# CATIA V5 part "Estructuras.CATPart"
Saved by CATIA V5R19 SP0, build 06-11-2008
Part number: Estructuras
Bounding box of the stored display mesh (mm): x -165.206 to 53.773, y -15.481 to 36, z -5 to 20
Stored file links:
  G:\Prácticas\0068\68_v5r19\Estructuras.CATPart
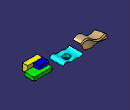
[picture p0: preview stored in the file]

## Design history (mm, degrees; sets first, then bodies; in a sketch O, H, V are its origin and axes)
Set1
  Sketch1 on zx-plane, origin (0, 0, 0), H (-1, 0, 0), V (0, 0, 1)
    spline S1 through (25.3759, 1.956) (35.7609, 8.1375) (48.124, 3.0687) (61.3525, 4.5522) (71.9847, 1.956) (83.606, 6.5303)
  Extrude1: Lim1 36, Lim2 5, Element1 Sketch1, Direction zx-plane
  Sketch2 on xy-plane, origin (0, 0, 0), H (1, 0, 0), V (0, 1, 0)
    circle A1 centre (-52.8527, 17.16) radius 9.9795
  Project1: Support Extrude1, Direction (0, 0, 1), ToProject Sketch2
  Split1: ToCut Extrude1, Cutting Project1
  Extrude2: Lim1 36, Lim2 5, Element1 Sketch2, Direction xy-plane
  Trim1: Trimmed (Split1; Extrude2)
Set2
  Sketch3 on zx-plane, origin (0, 0, 0), H (-1, 0, 0), V (0, 0, 1)
    spline S1 through (99.8383, 10.3678) (106.3011, 14.7785) (119.3682, 15.8789) (133.4063, 5.1188) (150.5796, 0.1019) (164.2796, 5.5048)
  Sweep1: type Segment, Angle 90, AngleEnd 100, Length1 35, Length2 10, DraftDirection (0, 0, 1), GuideCrv Sketch3
  CurvePar1: Support Sweep1, Offset1 12, Offset2 20, Offset edge of Sweep1
  Sweep2: type Segment, Angle 35, Length1 30, Length2 5, DraftDirection (0, 0, 1), GuideCrv CurvePar1
  Fillet1: type BiTangent, Element1 Sweep2, Element2 Sweep1, Radius 5
  Intersect1: ToIntersect1 xy-plane, ToIntersect2 Fillet1
  Extract1: ExtractElem edge of Intersect1
  Split2: ToCut Fillet1, Cutting Extract1
Set3
  Sketch4 on zx-plane, origin (0, 0, 0), H (-1, 0, 0), V (0, 0, 1)
    spline S1 through (25.3759, 1.956) (35.7609, 8.1375) (48.124, 3.0687) (61.3525, 4.5522) (71.9847, 1.956) (83.606, 6.5303)
  Extrude3: Lim1 36, Lim2 5, Element1 Sketch4, Direction zx-plane
  Sketch5 on xy-plane, origin (0, 0, 0), H (1, 0, 0), V (0, 1, 0)
    circle A1 centre (-52.8527, 17.16) radius 9.9795
  Project2: Support Extrude3, Direction (0, 0, 1), ToProject Sketch5
  Split3: ToCut Extrude3, Cutting Project2
  Extrude4: Lim1 36, Lim2 5, Element1 Sketch5, Direction xy-plane
  Trim2: Trimmed (Split3; Extrude4)
Set4
  Sketch6 on zx-plane, origin (0, 0, 0), H (-1, 0, 0), V (0, 0, 1)
    spline S1 through (25.3759, 1.956) (35.7609, 8.1375) (48.124, 3.0687) (61.3525, 4.5522) (71.9847, 1.956) (83.606, 6.5303)
  Extrude5: Lim1 36, Lim2 5, Element1 Sketch6, Direction zx-plane
  Sketch7 on xy-plane, origin (0, 0, 0), H (1, 0, 0), V (0, 1, 0)
    circle A1 centre (-52.8527, 17.16) radius 9.9795
  Project3: Support Extrude5, Direction (0, 0, 1), ToProject Sketch7
  Split4: ToCut Extrude5, Cutting Project3
  Extrude6: Lim1 36, Lim2 5, Element1 Sketch7, Direction xy-plane
  Trim3: Trimmed (Split4; Extrude6)
Body1 (main body)
  Sketch8 on xy-plane, origin (0, 0, 0), H (1, 0, 0), V (0, 1, 0)
    line L1 (0, 0) -> (53.7732, 0)
    line L2 (53.7732, 0) -> (53.7732, 28.7124)
    line L3 (53.7732, 28.7124) -> (0, 28.7124)
    line L4 (0, 28.7124) -> (0, 0)
    horizontal: L1 H, L3 H
    vertical: L2 V, L4 V
  Pad1: profile Sketch8, direction (0, 0, 1), length 10
Body2
  Sketch9 on end face of Pad1, origin (0, 0, 10), H (1, 0, 0), V (0, 1, 0)
    line L1 (0, 0) -> (27.5082, 0)
    line L2 (27.5082, 0) -> (27.5082, 17.7669)
    line L3 (27.5082, 17.7669) -> (0, 17.7669)
    line L4 (0, 17.7669) -> (0, 0)
    horizontal: L1 H, L3 H
    vertical: L2 V, L4 V
  Pad2: profile Sketch9, direction (0, 0, 1), length 10
  Fillet2: radius 5, on edge [face of Pad2 from Sketch9.L3 | face of Pad2 from Sketch9.L2]
Body3
  Sketch10 on end face of Pad1, origin (0, 0, 10), H (1, 0, 0), V (0, 1, 0)
    line L1 (0, 0) -> (43.7446, 0)
    line L2 (43.7446, 0) -> (43.7446, -15.4814)
    line L3 (43.7446, -15.4814) -> (0, -15.4814)
    line L4 (0, -15.4814) -> (0, 0)
    horizontal: L1 H, L3 H
    vertical: L2 V, L4 V
  Pocket1: profile Sketch10, direction (0, 0, -1), length 10, mirrored extent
